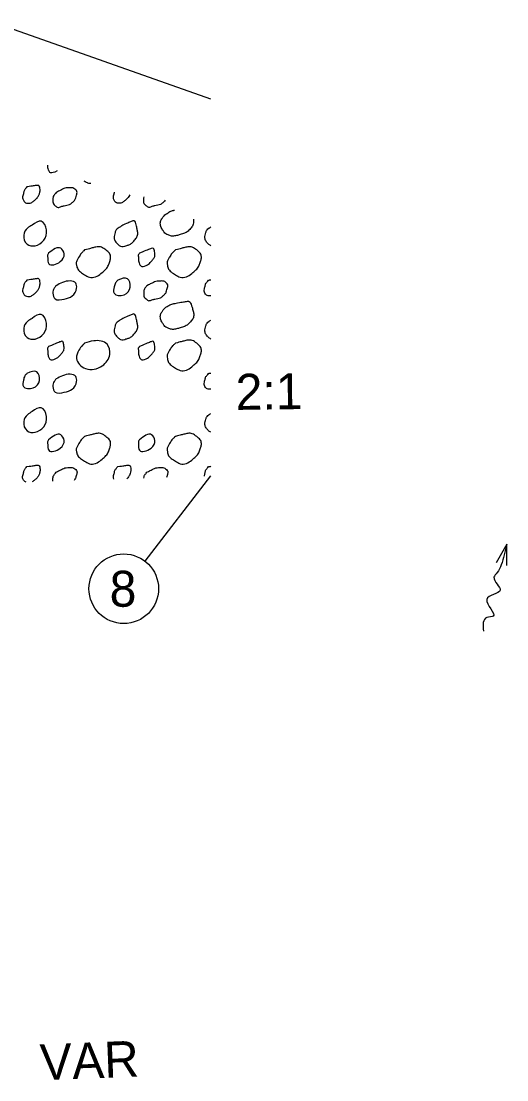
# Model space of a CAD drawing. Extents: x -1270 to 3371, y -118 to 220.
# Drawn here: x 99.09 to 118.01, y 112.79 to 154 of the extents above; entities that cross this region are included whole.
import ezdxf

# ---------------------------------------------------------------- set-up
doc = ezdxf.new("R2010")
doc.units = 0
for name, color, linetype in [('GE_P_Alignment', 7, 'Continuous'), ('GE_P_Alignment_100_Bearings', 7, 'Continuous'), ('GE_P_Alignment_100_Distances', 7, 'Continuous'), ('TX_P_1', 7, 'Continuous')]:
    doc.layers.add(name, color=color, linetype=linetype)

msp = doc.modelspace()

# ---------------------------------------------------------------- linework, layer by layer
at = {"layer": 'GE_P_Alignment'}
msp.add_line((103.916, 132.978), (106.483, 136.296), dxfattribs=at)
at = {"layer": 'GE_P_Alignment_100_Bearings'}
for points, degree in [([(100.492, 148.173), (100.365, 148.101), (100.205, 148.079), (100.163, 148.186), (100.136, 148.254), (100.129, 148.323), (100.125, 148.393)], 3), ([(99.315, 147.551), (99.443, 147.57), (99.57, 147.59), (99.697, 147.607), (99.811, 147.623), (99.837, 147.377), (99.801, 147.279), (99.762, 147.171), (99.663, 147.063), (99.561, 146.985), (99.456, 146.904), (99.235, 146.918), (99.175, 147.041), (99.136, 147.119), (99.155, 147.209), (99.177, 147.287), (99.192, 147.342), (99.199, 147.405), (99.235, 147.451), (99.262, 147.484), (99.289, 147.518), (99.315, 147.551)], 3), ([(101.804, 147.679), (101.732, 147.682), (101.663, 147.701), (101.6, 147.738), (101.582, 147.749), (101.563, 147.76), (101.545, 147.772)], 3), ([(100.453, 147.335), (100.536, 147.377), (100.619, 147.418), (100.703, 147.46), (100.794, 147.505), (100.904, 147.514), (101.004, 147.517), (101.077, 147.519), (101.148, 147.502), (101.215, 147.436), (101.275, 147.376), (101.266, 147.296), (101.249, 147.233), (101.219, 147.128), (101.18, 147.021), (101.078, 146.936), (100.978, 146.853), (100.872, 146.841), (100.765, 146.816), (100.652, 146.79), (100.523, 146.723), (100.413, 146.822), (100.34, 146.888), (100.325, 146.964), (100.327, 147.038), (100.329, 147.104), (100.337, 147.183), (100.379, 147.238), (100.403, 147.271), (100.428, 147.303), (100.453, 147.335)], 3), ([(103.323, 147.245), (103.277, 147.149), (103.188, 147.055), (103.097, 146.985), (102.992, 146.904), (102.771, 146.918), (102.71, 147.041), (102.672, 147.119), (102.691, 147.209), (102.713, 147.287), (102.718, 147.307), (102.723, 147.328), (102.728, 147.348)], 3), ([(104.702, 147.036), (104.679, 147.001), (104.651, 146.967), (104.614, 146.936), (104.514, 146.853), (104.408, 146.841), (104.3, 146.816), (104.188, 146.79), (104.059, 146.723), (103.949, 146.822), (103.876, 146.888), (103.861, 146.964), (103.863, 147.038), (103.864, 147.077), (103.867, 147.121), (103.878, 147.161)], 3), ([(105.798, 146.296), (105.817, 146.177), (105.788, 146.041), (105.692, 145.935), (105.559, 145.787), (105.411, 145.731), (105.246, 145.682), (105.105, 145.641), (104.947, 145.625), (104.806, 145.685), (104.721, 145.721), (104.659, 145.783), (104.607, 145.863), (104.521, 145.997), (104.495, 146.182), (104.57, 146.308), (104.62, 146.392), (104.688, 146.466), (104.775, 146.521), (104.849, 146.568), (104.919, 146.612), (105.001, 146.63), (105.023, 146.634), (105.045, 146.639), (105.067, 146.644)], 3), ([(103.055, 146.063), (103.173, 146.113), (103.29, 146.164), (103.407, 146.214), (103.529, 146.266), (103.588, 145.999), (103.615, 145.876), (103.643, 145.745), (103.609, 145.598), (103.503, 145.471), (103.403, 145.351), (103.289, 145.294), (103.17, 145.258), (103.074, 145.229), (102.953, 145.224), (102.859, 145.317), (102.745, 145.43), (102.702, 145.562), (102.725, 145.676), (102.744, 145.767), (102.786, 145.887), (102.871, 145.944), (102.933, 145.985), (102.994, 146.023), (103.055, 146.063)], 3), ([(106.483, 145.259), (106.452, 145.271), (106.422, 145.29), (106.394, 145.317), (106.281, 145.43), (106.238, 145.562), (106.261, 145.676), (106.279, 145.767), (106.322, 145.887), (106.407, 145.944), (106.432, 145.961), (106.458, 145.977), (106.483, 145.994)], 3), ([(101.56, 145.094), (101.679, 145.126), (101.798, 145.156), (101.916, 145.187), (102.089, 145.232), (102.264, 145.2), (102.437, 145.056), (102.571, 144.943), (102.58, 144.777), (102.545, 144.653), (102.5, 144.496), (102.401, 144.348), (102.249, 144.218), (102.059, 144.056), (101.795, 143.992), (101.6, 144.107), (101.443, 144.201), (101.277, 144.34), (101.246, 144.506), (101.227, 144.608), (101.281, 144.728), (101.341, 144.824), (101.384, 144.892), (101.423, 144.961), (101.48, 145.016), (101.506, 145.042), (101.533, 145.068), (101.56, 145.094)], 3), ([(103.697, 144.968), (103.855, 145.032), (104.014, 145.1), (104.172, 145.161), (104.25, 145.19), (104.291, 145.017), (104.298, 144.942), (104.307, 144.843), (104.231, 144.739), (104.149, 144.64), (104.037, 144.506), (103.757, 144.408), (103.699, 144.556), (103.668, 144.634), (103.663, 144.715), (103.659, 144.796), (103.658, 144.836), (103.643, 144.88), (103.664, 144.916), (103.674, 144.935), (103.686, 144.951), (103.697, 144.968)], 3), ([(105.096, 145.094), (105.215, 145.126), (105.333, 145.156), (105.452, 145.187), (105.625, 145.232), (105.8, 145.2), (105.973, 145.056), (106.107, 144.943), (106.116, 144.777), (106.08, 144.653), (106.035, 144.496), (105.936, 144.348), (105.784, 144.218), (105.595, 144.056), (105.331, 143.992), (105.136, 144.107), (104.979, 144.201), (104.812, 144.34), (104.782, 144.506), (104.763, 144.608), (104.817, 144.728), (104.877, 144.824), (104.92, 144.892), (104.958, 144.961), (105.015, 145.016), (105.042, 145.042), (105.069, 145.068), (105.096, 145.094)], 3), ([(99.315, 143.921), (99.443, 143.939), (99.57, 143.96), (99.697, 143.977), (99.811, 143.992), (99.837, 143.747), (99.801, 143.648), (99.762, 143.54), (99.663, 143.432), (99.561, 143.354), (99.456, 143.274), (99.235, 143.287), (99.175, 143.411), (99.136, 143.489), (99.155, 143.579), (99.177, 143.657), (99.192, 143.712), (99.199, 143.775), (99.235, 143.82), (99.262, 143.854), (99.289, 143.887), (99.315, 143.921)], 3), ([(103.989, 143.704), (104.072, 143.746), (104.155, 143.788), (104.239, 143.829), (104.33, 143.875), (104.44, 143.884), (104.539, 143.887), (104.613, 143.889), (104.684, 143.872), (104.75, 143.806), (104.811, 143.746), (104.802, 143.666), (104.784, 143.603), (104.755, 143.498), (104.716, 143.391), (104.614, 143.306), (104.514, 143.223), (104.408, 143.211), (104.3, 143.186), (104.188, 143.16), (104.059, 143.093), (103.949, 143.192), (103.876, 143.257), (103.861, 143.333), (103.863, 143.408), (103.865, 143.474), (103.873, 143.552), (103.914, 143.608), (103.939, 143.64), (103.964, 143.672), (103.989, 143.704)], 3), ([(106.483, 143.304), (106.387, 143.299), (106.285, 143.333), (106.246, 143.411), (106.208, 143.489), (106.227, 143.579), (106.249, 143.657), (106.264, 143.712), (106.271, 143.775), (106.307, 143.82), (106.334, 143.854), (106.36, 143.887), (106.387, 143.921)], 3), ([(106.387, 143.921), (106.419, 143.926), (106.451, 143.93), (106.483, 143.935)], 2), ([(105.075, 143.015), (105.227, 143.041), (105.378, 143.07), (105.529, 143.091), (105.681, 143.112), (105.751, 142.853), (105.789, 142.711), (105.823, 142.582), (105.801, 142.425), (105.692, 142.304), (105.559, 142.157), (105.411, 142.1), (105.246, 142.052), (105.105, 142.01), (104.947, 141.995), (104.806, 142.054), (104.721, 142.09), (104.659, 142.152), (104.607, 142.233), (104.521, 142.366), (104.495, 142.551), (104.57, 142.678), (104.62, 142.761), (104.688, 142.835), (104.775, 142.891), (104.849, 142.938), (104.919, 142.982), (105.001, 142.999), (105.029, 143.005), (105.056, 143.011), (105.084, 143.017)], 3), ([(103.055, 142.433), (103.173, 142.483), (103.29, 142.533), (103.407, 142.583), (103.529, 142.636), (103.588, 142.369), (103.615, 142.245), (103.643, 142.114), (103.609, 141.967), (103.503, 141.84), (103.403, 141.721), (103.289, 141.664), (103.17, 141.628), (103.074, 141.599), (102.953, 141.594), (102.859, 141.687), (102.745, 141.799), (102.702, 141.931), (102.725, 142.046), (102.744, 142.137), (102.786, 142.257), (102.871, 142.313), (102.933, 142.354), (102.994, 142.393), (103.055, 142.433)], 3), ([(106.483, 141.628), (106.452, 141.64), (106.422, 141.659), (106.394, 141.687), (106.281, 141.799), (106.238, 141.931), (106.261, 142.046), (106.279, 142.137), (106.322, 142.257), (106.407, 142.313), (106.432, 142.33), (106.458, 142.347), (106.483, 142.363)], 3), ([(100.161, 141.338), (100.32, 141.402), (100.478, 141.47), (100.636, 141.53), (100.714, 141.56), (100.755, 141.386), (100.762, 141.312), (100.771, 141.212), (100.695, 141.108), (100.613, 141.009), (100.501, 140.875), (100.221, 140.778), (100.163, 140.925), (100.132, 141.003), (100.127, 141.084), (100.124, 141.165), (100.122, 141.205), (100.107, 141.25), (100.128, 141.286), (100.138, 141.304), (100.15, 141.32), (100.161, 141.338)], 3), ([(103.697, 141.338), (103.855, 141.402), (104.014, 141.47), (104.172, 141.53), (104.25, 141.56), (104.291, 141.386), (104.298, 141.312), (104.307, 141.212), (104.231, 141.108), (104.149, 141.009), (104.037, 140.875), (103.757, 140.778), (103.699, 140.925), (103.668, 141.003), (103.663, 141.084), (103.659, 141.165), (103.658, 141.205), (103.643, 141.25), (103.664, 141.286), (103.674, 141.304), (103.686, 141.32), (103.697, 141.338)], 3), ([(105.096, 141.463), (105.215, 141.495), (105.333, 141.526), (105.452, 141.557), (105.625, 141.602), (105.8, 141.57), (105.973, 141.425), (106.107, 141.313), (106.116, 141.147), (106.08, 141.023), (106.035, 140.866), (105.936, 140.717), (105.784, 140.588), (105.595, 140.425), (105.331, 140.362), (105.136, 140.477), (104.979, 140.57), (104.812, 140.71), (104.782, 140.875), (104.763, 140.978), (104.817, 141.098), (104.877, 141.193), (104.92, 141.262), (104.958, 141.331), (105.015, 141.386), (105.042, 141.412), (105.069, 141.438), (105.096, 141.463)], 3), ([(106.483, 139.674), (106.387, 139.668), (106.285, 139.702), (106.246, 139.78), (106.208, 139.858), (106.227, 139.948), (106.249, 140.026), (106.264, 140.081), (106.271, 140.144), (106.307, 140.19), (106.334, 140.223), (106.36, 140.257), (106.387, 140.29)], 3), ([(106.387, 140.29), (106.419, 140.295), (106.451, 140.3), (106.483, 140.305)], 2), ([(106.483, 137.998), (106.452, 138.01), (106.422, 138.029), (106.394, 138.056), (106.281, 138.169), (106.238, 138.301), (106.261, 138.415), (106.279, 138.506), (106.322, 138.626), (106.407, 138.683), (106.432, 138.7), (106.458, 138.716), (106.483, 138.733)], 3), ([(101.56, 137.833), (101.679, 137.865), (101.798, 137.896), (101.916, 137.926), (102.089, 137.971), (102.264, 137.939), (102.437, 137.795), (102.571, 137.682), (102.58, 137.516), (102.545, 137.392), (102.5, 137.235), (102.401, 137.087), (102.249, 136.957), (102.059, 136.795), (101.795, 136.731), (101.6, 136.846), (101.443, 136.94), (101.277, 137.08), (101.246, 137.245), (101.227, 137.347), (101.281, 137.467), (101.341, 137.563), (101.384, 137.631), (101.423, 137.7), (101.48, 137.755), (101.506, 137.781), (101.533, 137.807), (101.56, 137.833)], 3), ([(105.096, 137.833), (105.215, 137.865), (105.333, 137.896), (105.452, 137.926), (105.625, 137.971), (105.8, 137.939), (105.973, 137.795), (106.107, 137.682), (106.116, 137.516), (106.08, 137.392), (106.035, 137.235), (105.936, 137.087), (105.784, 136.957), (105.595, 136.795), (105.331, 136.731), (105.136, 136.846), (104.979, 136.94), (104.812, 137.08), (104.782, 137.245), (104.763, 137.347), (104.817, 137.467), (104.877, 137.563), (104.92, 137.631), (104.958, 137.7), (105.015, 137.755), (105.042, 137.781), (105.069, 137.807), (105.096, 137.833)], 3), ([(99.28, 136.062), (99.233, 136.079), (99.195, 136.108), (99.175, 136.15), (99.136, 136.228), (99.155, 136.318), (99.177, 136.396), (99.192, 136.451), (99.199, 136.514), (99.235, 136.559), (99.262, 136.593), (99.289, 136.626), (99.315, 136.66)], 3), ([(99.315, 136.66), (99.443, 136.678), (99.57, 136.699), (99.697, 136.716), (99.811, 136.731), (99.837, 136.486), (99.801, 136.387), (99.762, 136.279), (99.663, 136.171), (99.561, 136.093), (99.55, 136.084), (99.536, 136.077), (99.522, 136.07)], 3), ([(100.329, 136.096), (100.327, 136.113), (100.327, 136.13), (100.327, 136.147), (100.329, 136.213), (100.337, 136.291), (100.379, 136.347), (100.403, 136.379), (100.428, 136.411), (100.453, 136.443)], 3), ([(100.453, 136.443), (100.536, 136.485), (100.619, 136.527), (100.703, 136.568), (100.794, 136.614), (100.904, 136.623), (101.004, 136.626), (101.077, 136.628), (101.148, 136.611), (101.215, 136.545), (101.275, 136.485), (101.266, 136.405), (101.249, 136.342), (101.228, 136.267), (101.202, 136.191), (101.152, 136.123)], 3), ([(102.701, 136.173), (102.676, 136.245), (102.693, 136.326), (102.713, 136.396), (102.728, 136.451), (102.735, 136.514), (102.771, 136.559), (102.798, 136.593), (102.824, 136.626), (102.851, 136.66)], 3), ([(102.851, 136.66), (102.978, 136.678), (103.106, 136.699), (103.233, 136.716), (103.346, 136.731), (103.373, 136.486), (103.337, 136.387), (103.312, 136.319), (103.263, 136.25), (103.205, 136.19)], 3), ([(103.867, 136.211), (103.873, 136.26), (103.886, 136.309), (103.914, 136.347), (103.939, 136.379), (103.964, 136.411), (103.989, 136.443)], 3), ([(103.989, 136.443), (104.072, 136.485), (104.155, 136.527), (104.239, 136.568), (104.33, 136.614), (104.44, 136.623), (104.539, 136.626), (104.613, 136.628), (104.684, 136.611), (104.75, 136.545), (104.811, 136.485), (104.802, 136.405), (104.784, 136.342), (104.775, 136.308), (104.764, 136.274), (104.751, 136.24)], 3), ([(106.226, 136.288), (106.23, 136.325), (106.239, 136.362), (106.249, 136.396), (106.264, 136.451), (106.271, 136.514), (106.307, 136.559), (106.334, 136.593), (106.36, 136.626), (106.387, 136.66)], 3), ([(106.387, 136.66), (106.419, 136.665), (106.451, 136.669), (106.483, 136.674)], 2)]:
    msp.add_open_spline(points, degree=degree, dxfattribs=at)
for points in [[(99.52, 146.063), (99.871, 146.214), (100.079, 145.876), (99.967, 145.471), (99.634, 145.258), (99.323, 145.317), (99.19, 145.676), (99.335, 145.944), (99.52, 146.063)], [(100.161, 144.968), (100.636, 145.161), (100.762, 144.942), (100.613, 144.64), (100.163, 144.556), (100.124, 144.796), (100.128, 144.916), (100.161, 144.968)], [(100.453, 143.704), (100.703, 143.829), (101.004, 143.887), (101.215, 143.806), (101.249, 143.603), (101.078, 143.306), (100.765, 143.186), (100.413, 143.192), (100.327, 143.408), (100.379, 143.608), (100.453, 143.704)], [(102.851, 143.921), (103.233, 143.977), (103.337, 143.648), (103.097, 143.354), (102.71, 143.411), (102.713, 143.657), (102.771, 143.82), (102.851, 143.921)], [(99.52, 142.433), (99.871, 142.583), (100.079, 142.245), (99.967, 141.84), (99.634, 141.628), (99.323, 141.687), (99.19, 142.046), (99.335, 142.313), (99.52, 142.433)], [(101.56, 141.463), (101.916, 141.557), (102.437, 141.425), (102.545, 141.023), (102.249, 140.588), (101.6, 140.477), (101.246, 140.875), (101.341, 141.193), (101.48, 141.386), (101.56, 141.463)], [(99.315, 140.29), (99.697, 140.346), (99.801, 140.018), (99.561, 139.724), (99.175, 139.78), (99.177, 140.026), (99.235, 140.19), (99.315, 140.29)], [(100.453, 140.074), (100.703, 140.199), (101.004, 140.256), (101.215, 140.175), (101.249, 139.972), (101.078, 139.675), (100.765, 139.555), (100.413, 139.561), (100.327, 139.777), (100.379, 139.977), (100.453, 140.074)], [(99.52, 138.802), (99.871, 138.953), (100.079, 138.615), (99.967, 138.21), (99.634, 137.997), (99.323, 138.056), (99.19, 138.415), (99.335, 138.683), (99.52, 138.802)], [(100.161, 137.707), (100.636, 137.9), (100.762, 137.681), (100.613, 137.379), (100.163, 137.295), (100.124, 137.535), (100.128, 137.655), (100.161, 137.707)], [(103.697, 137.707), (104.172, 137.9), (104.298, 137.681), (104.149, 137.379), (103.699, 137.295), (103.659, 137.535), (103.664, 137.655), (103.697, 137.707)]]:
    msp.add_spline(points, degree=3, dxfattribs=at)
at = {"layer": 'GE_P_Alignment_100_Distances'}
for p, q in [((118.008, 133.636), (117.591, 132.919)), ((118.006, 132.807), (118.008, 133.636))]:
    msp.add_line(p, q, dxfattribs=at)
msp.add_spline([(118.008, 133.636), (117.788, 132.834), (117.63, 132.536), (117.506, 132.354), (117.75, 131.848), (117.225, 131.488), (117.477, 130.84), (117.231, 130.789), (117.093, 130.257)], degree=3, dxfattribs=at)
at = {"layer": 'TX_P_1'}
msp.add_line((106.483, 150.963), (75.765, 161.784), dxfattribs=at)
msp.add_circle((103.087, 131.907), 1.355, dxfattribs=at)

# ---------------------------------------------------------------- texts
for s, rotation, p in [('2:1', 0.7499, (107.454, 138.868)), ('VAR', 2.2498, (99.851, 112.769))]:
    msp.add_text(s, height=1.4, rotation=rotation, dxfattribs=at).set_placement(p)
msp.add_text('8', height=1.4, dxfattribs=at).set_placement((102.537, 131.207))

doc.saveas('drawing.dxf')
